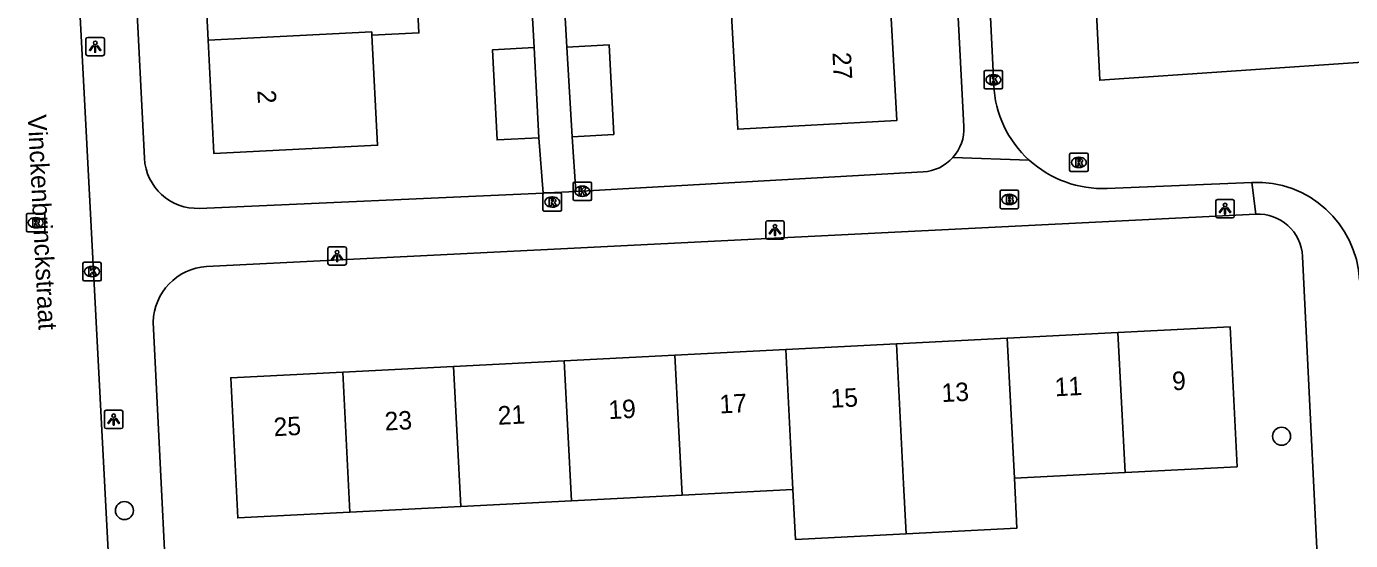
# Model space of a CAD drawing. Extents: x 160557 to 161245, y 385330 to 386505.
# Drawn here: x 161000.9 to 161072.6, y 385390.8 to 385418.6 of the extents above; entities that cross this region are included whole.
import ezdxf

# ---------------------------------------------------------------- set-up
doc = ezdxf.new("R2010")
doc.units = 0
for name, color, linetype in [('IMGEO_Boom', 7, 'Continuous'), ('IMGEO_Brandkraan', 7, 'Continuous'), ('IMGEO_Kolk', 7, 'Continuous'), ('IMGEO_Lichtpunt', 7, 'Continuous'), ('IMGEO_Openbare_ruimte_label', 7, 'Continuous'), ('IMGEO_Pand', 7, 'Continuous'), ('IMGEO_Pand_nummerreeks', 7, 'Continuous'), ('IMGEO_Rijbaan_lokaal_open', 7, 'Continuous'), ('IMGEO_Rioolput', 7, 'Continuous'), ('IMGEO_Voetpad_open', 7, 'Continuous')]:
    doc.layers.add(name, color=color, linetype=linetype)

msp = doc.modelspace()

# ---------------------------------------------------------------- linework, layer by layer
at = {"layer": 'IMGEO_Boom'}
for centre in [(161068.856, 385396.421), (161006.241, 385392.397)]:
    msp.add_circle(centre, 0.489, dxfattribs=at)
at = {"layer": 'IMGEO_Brandkraan'}
for p, q in [((161053.623, 385408.813), (161053.623, 385409.665)), ((161053.698, 385409.739), (161054.55, 385409.739)), ((161054.624, 385409.665), (161054.624, 385408.813)), ((161054.134, 385408.959), (161054.109, 385408.959)), ((161054.111, 385409.519), (161054.136, 385409.519)), ((161054.55, 385408.739), (161053.698, 385408.739))]:
    msp.add_line(p, q, dxfattribs=at)
for points in [[(161053.623, 385408.813), (161053.623, 385409.665)], [(161053.698, 385409.739), (161054.55, 385409.739)], [(161054.624, 385409.665), (161054.624, 385408.813)], [(161053.971, 385409.439), (161053.971, 385409.039), (161054.184, 385409.039)], [(161054.202, 385409.439), (161053.971, 385409.439)], [(161054.15, 385409.358), (161054.096, 385409.358), (161054.096, 385409.282)], [(161054.096, 385409.282), (161054.149, 385409.282)], [(161054.158, 385409.206), (161054.096, 385409.206), (161054.096, 385409.125)], [(161054.096, 385409.125), (161054.158, 385409.125)], [(161054.55, 385408.739), (161053.698, 385408.739)]]:
    msp.add_lwpolyline(points, dxfattribs=at)
for centre, radius, start, end in [((161053.7, 385409.663), 0.0765, 91.55205, 178.44795), ((161053.7, 385409.663), 0.0765, 91.55205, 178.44795), ((161054.548, 385409.663), 0.0765, 1.55205, 88.44795), ((161054.548, 385409.663), 0.0765, 1.55205, 88.44795), ((161054.151, 385409.32), 0.0379, 267.82845, 90.93552), ((161054.159, 385409.165), 0.0404, 269.87594, 90.50774), ((161054.19, 385409.29), 0.251, 268.66757, 293.53466), ((161054.206, 385409.294), 0.145, 59.4692, 91.53667), ((161054.231, 385409.341), 0.0922, 285.51372, 58.15012), ((161054.236, 385409.149), 0.105, 301.31148, 78.98903), ((161053.7, 385408.815), 0.0765, 181.55205, 268.44795), ((161053.7, 385408.815), 0.0765, 181.55205, 268.44795), ((161054.548, 385408.815), 0.0765, 271.55205, 358.44795), ((161054.548, 385408.815), 0.0765, 271.55205, 358.44795)]:
    msp.add_arc(centre, radius, start, end, dxfattribs=at)
for centre, major_axis, ratio, start_param, end_param in [((161054.11, 385409.239), (-0.387, 0.002), 0.722429, 4.712389, 7.853982), ((161054.135, 385409.239), (-0.39, 0.002), 0.717154, 1.570796, 4.712389)]:
    msp.add_ellipse(centre, major_axis=major_axis, ratio=ratio, start_param=start_param, end_param=end_param, dxfattribs=at)
at = {"layer": 'IMGEO_Kolk'}
for p, q in [((161052.764, 385415.297), (161052.764, 385416.149)), ((161052.839, 385416.223), (161053.691, 385416.223)), ((161053.765, 385416.149), (161053.765, 385415.297)), ((161053.275, 385415.443), (161053.25, 385415.443)), ((161053.252, 385416.003), (161053.277, 385416.003)), ((161053.691, 385415.223), (161052.839, 385415.223)), ((161030.52, 385409.255), (161030.52, 385410.107)), ((161030.595, 385410.181), (161031.447, 385410.181)), ((161031.008, 385409.961), (161031.033, 385409.961)), ((161031.521, 385410.107), (161031.521, 385409.255)), ((161031.447, 385409.181), (161030.595, 385409.181)), ((161031.031, 385409.401), (161031.006, 385409.401)), ((161003.987, 385404.911), (161003.987, 385405.763)), ((161004.062, 385405.837), (161004.914, 385405.837)), ((161004.475, 385405.617), (161004.5, 385405.617)), ((161004.988, 385405.763), (161004.988, 385404.911)), ((161004.914, 385404.837), (161004.062, 385404.837)), ((161004.498, 385405.057), (161004.473, 385405.057))]:
    msp.add_line(p, q, dxfattribs=at)
for points in [[(161052.764, 385415.297), (161052.764, 385416.149)], [(161052.839, 385416.223), (161053.691, 385416.223)], [(161053.765, 385416.149), (161053.765, 385415.297)], [(161053.085, 385415.923), (161053.208, 385415.923), (161053.208, 385415.772), (161053.338, 385415.923), (161053.502, 385415.923), (161053.356, 385415.772), (161053.509, 385415.523), (161053.357, 385415.523), (161053.272, 385415.687), (161053.208, 385415.62), (161053.208, 385415.523), (161053.085, 385415.523), (161053.085, 385415.923)], [(161053.691, 385415.223), (161052.839, 385415.223)], [(161030.52, 385409.255), (161030.52, 385410.107)], [(161030.595, 385410.181), (161031.447, 385410.181)], [(161030.841, 385409.881), (161030.964, 385409.881), (161030.964, 385409.73), (161031.094, 385409.881), (161031.258, 385409.881), (161031.112, 385409.73), (161031.265, 385409.481), (161031.113, 385409.481), (161031.028, 385409.645), (161030.964, 385409.578), (161030.964, 385409.481), (161030.841, 385409.481), (161030.841, 385409.881)], [(161031.521, 385410.107), (161031.521, 385409.255)], [(161031.447, 385409.181), (161030.595, 385409.181)], [(161003.987, 385404.911), (161003.987, 385405.763)], [(161004.062, 385405.837), (161004.914, 385405.837)], [(161004.308, 385405.537), (161004.431, 385405.537), (161004.431, 385405.386), (161004.561, 385405.537), (161004.725, 385405.537), (161004.579, 385405.386), (161004.732, 385405.137), (161004.58, 385405.137), (161004.495, 385405.301), (161004.431, 385405.234), (161004.431, 385405.137), (161004.308, 385405.137), (161004.308, 385405.537)], [(161004.988, 385405.763), (161004.988, 385404.911)], [(161004.914, 385404.837), (161004.062, 385404.837)]]:
    msp.add_lwpolyline(points, dxfattribs=at)
for centre, start, end in [((161052.841, 385416.147), 91.55205, 178.44795), ((161052.841, 385416.147), 91.55205, 178.44795), ((161053.689, 385416.147), 1.55205, 88.44795), ((161053.689, 385416.147), 1.55205, 88.44795), ((161052.841, 385415.299), 181.55205, 268.44795), ((161052.841, 385415.299), 181.55205, 268.44795), ((161053.689, 385415.299), 271.55205, 358.44795), ((161053.689, 385415.299), 271.55205, 358.44795), ((161030.597, 385410.105), 91.55205, 178.44795), ((161030.597, 385410.105), 91.55205, 178.44795), ((161031.445, 385410.105), 1.55205, 88.44795), ((161031.445, 385410.105), 1.55205, 88.44795), ((161030.597, 385409.257), 181.55205, 268.44795), ((161030.597, 385409.257), 181.55205, 268.44795), ((161031.445, 385409.257), 271.55205, 358.44795), ((161031.445, 385409.257), 271.55205, 358.44795), ((161004.064, 385405.761), 91.55205, 178.44795), ((161004.064, 385405.761), 91.55205, 178.44795), ((161004.912, 385405.761), 1.55205, 88.44795), ((161004.912, 385405.761), 1.55205, 88.44795), ((161004.064, 385404.913), 181.55205, 268.44795), ((161004.064, 385404.913), 181.55205, 268.44795), ((161004.912, 385404.913), 271.55205, 358.44795), ((161004.912, 385404.913), 271.55205, 358.44795)]:
    msp.add_arc(centre, 0.0765, start, end, dxfattribs=at)
for centre, major_axis, ratio, start_param, end_param in [((161053.251, 385415.723), (-0.387, 0.002), 0.722429, 4.712389, 7.853982), ((161053.276, 385415.723), (-0.39, 0.002), 0.717154, 1.570796, 4.712389), ((161031.007, 385409.681), (-0.387, 0.002), 0.722429, 4.712389, 7.853982), ((161031.032, 385409.681), (-0.39, 0.002), 0.717154, 1.570796, 4.712389), ((161004.474, 385405.337), (-0.387, 0.002), 0.722429, 4.712389, 7.853982), ((161004.499, 385405.337), (-0.39, 0.002), 0.717154, 1.570796, 4.712389)]:
    msp.add_ellipse(centre, major_axis=major_axis, ratio=ratio, start_param=start_param, end_param=end_param, dxfattribs=at)
at = {"layer": 'IMGEO_Lichtpunt'}
for p, q in [((161004.159, 385417.918), (161004.159, 385417.111)), ((161004.159, 385417.918), (161004.159, 385417.111)), ((161005.061, 385418.013), (161004.253, 385418.013)), ((161005.061, 385418.013), (161004.253, 385418.013)), ((161005.155, 385417.111), (161005.155, 385417.918)), ((161005.155, 385417.111), (161005.155, 385417.918)), ((161004.253, 385417.017), (161005.061, 385417.017)), ((161004.253, 385417.017), (161005.061, 385417.017)), ((161065.3, 385409.143), (161065.3, 385408.336)), ((161065.3, 385409.143), (161065.3, 385408.336)), ((161066.202, 385409.238), (161065.394, 385409.238)), ((161066.202, 385409.238), (161065.394, 385409.238)), ((161066.296, 385408.336), (161066.296, 385409.143)), ((161066.296, 385408.336), (161066.296, 385409.143)), ((161065.394, 385408.242), (161066.202, 385408.242)), ((161065.394, 385408.242), (161066.202, 385408.242)), ((161040.945, 385407.989), (161040.945, 385407.182)), ((161040.945, 385407.989), (161040.945, 385407.182)), ((161041.847, 385408.084), (161041.039, 385408.084)), ((161041.847, 385408.084), (161041.039, 385408.084)), ((161041.941, 385407.182), (161041.941, 385407.989)), ((161041.941, 385407.182), (161041.941, 385407.989)), ((161041.039, 385407.088), (161041.847, 385407.088)), ((161041.039, 385407.088), (161041.847, 385407.088)), ((161017.253, 385406.584), (161017.253, 385405.777)), ((161017.253, 385406.584), (161017.253, 385405.777)), ((161018.155, 385406.679), (161017.347, 385406.679)), ((161018.155, 385406.679), (161017.347, 385406.679)), ((161018.249, 385405.777), (161018.249, 385406.584)), ((161018.249, 385405.777), (161018.249, 385406.584)), ((161017.347, 385405.683), (161018.155, 385405.683)), ((161017.347, 385405.683), (161018.155, 385405.683)), ((161005.161, 385397.736), (161005.161, 385396.929)), ((161005.161, 385397.736), (161005.161, 385396.929)), ((161006.063, 385397.831), (161005.255, 385397.831)), ((161006.063, 385397.831), (161005.255, 385397.831)), ((161006.157, 385396.929), (161006.157, 385397.736)), ((161006.157, 385396.929), (161006.157, 385397.736)), ((161005.255, 385396.835), (161006.063, 385396.835)), ((161005.255, 385396.835), (161006.063, 385396.835))]:
    msp.add_line(p, q, dxfattribs=at)
for points in [[(161004.533, 385417.582), (161004.572, 385417.554), (161004.384, 385417.292), (161004.346, 385417.319), (161004.533, 385417.582)], [(161004.635, 385417.534), (161004.682, 385417.534), (161004.682, 385417.212), (161004.635, 385417.212), (161004.635, 385417.534)], [(161004.745, 385417.554), (161004.783, 385417.581), (161004.97, 385417.319), (161004.931, 385417.291), (161004.745, 385417.554)], [(161065.674, 385408.807), (161065.713, 385408.779), (161065.525, 385408.517), (161065.487, 385408.544), (161065.674, 385408.807)], [(161065.776, 385408.759), (161065.823, 385408.759), (161065.823, 385408.437), (161065.776, 385408.437), (161065.776, 385408.759)], [(161065.886, 385408.779), (161065.924, 385408.806), (161066.111, 385408.544), (161066.072, 385408.516), (161065.886, 385408.779)], [(161041.319, 385407.653), (161041.358, 385407.625), (161041.17, 385407.363), (161041.132, 385407.39), (161041.319, 385407.653)], [(161041.421, 385407.605), (161041.468, 385407.605), (161041.468, 385407.283), (161041.421, 385407.283), (161041.421, 385407.605)], [(161041.531, 385407.625), (161041.569, 385407.652), (161041.756, 385407.39), (161041.717, 385407.362), (161041.531, 385407.625)], [(161017.627, 385406.248), (161017.666, 385406.22), (161017.478, 385405.958), (161017.44, 385405.985), (161017.627, 385406.248)], [(161017.729, 385406.2), (161017.776, 385406.2), (161017.776, 385405.878), (161017.729, 385405.878), (161017.729, 385406.2)], [(161017.839, 385406.22), (161017.877, 385406.247), (161018.064, 385405.985), (161018.025, 385405.957), (161017.839, 385406.22)], [(161005.535, 385397.4), (161005.574, 385397.372), (161005.386, 385397.11), (161005.348, 385397.137), (161005.535, 385397.4)], [(161005.637, 385397.352), (161005.684, 385397.352), (161005.684, 385397.03), (161005.637, 385397.03), (161005.637, 385397.352)], [(161005.747, 385397.372), (161005.785, 385397.399), (161005.972, 385397.137), (161005.933, 385397.109), (161005.747, 385397.372)]]:
    msp.add_lwpolyline(points, dxfattribs=at)
for centre in [(161004.658, 385417.716), (161065.799, 385408.941), (161041.444, 385407.787), (161017.752, 385406.382), (161005.66, 385397.534)]:
    msp.add_circle(centre, 0.0994, dxfattribs=at)
for centre, start, end in [((161004.253, 385417.918), 90, 180), ((161004.253, 385417.918), 90, 180), ((161005.061, 385417.918), 0, 90), ((161005.061, 385417.918), 0, 90), ((161004.253, 385417.111), 180, 270), ((161004.253, 385417.111), 180, 270), ((161005.061, 385417.111), 270, 0), ((161005.061, 385417.111), 270, 360), ((161065.394, 385409.143), 90, 180), ((161065.394, 385409.143), 90, 180), ((161066.202, 385409.143), 0, 90), ((161066.202, 385409.143), 0, 90), ((161065.394, 385408.336), 180, 270), ((161065.394, 385408.336), 180, 270), ((161066.202, 385408.336), 270, 0), ((161066.202, 385408.336), 270, 360), ((161041.039, 385407.989), 90, 180), ((161041.039, 385407.989), 90, 180), ((161041.847, 385407.989), 0, 90), ((161041.847, 385407.989), 0, 90), ((161041.039, 385407.182), 180, 270), ((161041.039, 385407.182), 180, 270), ((161041.847, 385407.182), 270, 0), ((161041.847, 385407.182), 270, 360), ((161017.347, 385406.584), 90, 180), ((161017.347, 385406.584), 90, 180), ((161018.155, 385406.584), 0, 90), ((161018.155, 385406.584), 0, 90), ((161017.347, 385405.777), 180, 270), ((161017.347, 385405.777), 180, 270), ((161018.155, 385405.777), 270, 0), ((161018.155, 385405.777), 270, 360), ((161005.255, 385397.736), 90, 180), ((161005.255, 385397.736), 90, 180), ((161006.063, 385397.736), 0, 90), ((161006.063, 385397.736), 0, 90), ((161005.255, 385396.929), 180, 270), ((161005.255, 385396.929), 180, 270), ((161006.063, 385396.929), 270, 0), ((161006.063, 385396.929), 270, 360)]:
    msp.add_arc(centre, 0.0946, start, end, dxfattribs=at)
at = {"layer": 'IMGEO_Pand'}
for points in [[(161019.634, 385418.125), (161022.181, 385418.255), (161021.883, 385424.097), (161019.335, 385423.967), (161019.318, 385424.303)], [(161010.464, 385423.853), (161010.77, 385417.861)], [(161047.7, 385419.697), (161048.038, 385413.509), (161039.428, 385413.039), (161039.09, 385419.226)], [(161010.77, 385417.861), (161019.624, 385418.311), (161019.634, 385418.125)], [(161019.634, 385418.125), (161019.938, 385412.178), (161011.084, 385411.725), (161010.77, 385417.861)], [(161030.461, 385412.629), (161032.721, 385412.761), (161032.464, 385417.618), (161030.177, 385417.484)], [(161028.405, 385417.461), (161026.159, 385417.347), (161026.408, 385412.465), (161028.672, 385412.58)], [(161028.672, 385412.58), (161028.405, 385417.461)], [(161030.177, 385417.484), (161030.461, 385412.629)], [(161054.01, 385401.733), (161060.002, 385402.04)], [(161060.002, 385402.04), (161066.07, 385402.35), (161066.455, 385394.77), (161060.39, 385394.459)], [(161060.002, 385402.04), (161060.39, 385394.459)], [(161036.033, 385400.814), (161042.026, 385401.121)], [(161042.026, 385401.121), (161048.018, 385401.427)], [(161042.026, 385401.121), (161042.414, 385393.539)], [(161048.018, 385401.427), (161054.01, 385401.733)], [(161048.018, 385401.427), (161048.406, 385393.846), (161048.544, 385391.147)], [(161054.398, 385394.152), (161054.01, 385401.733)], [(161024.049, 385400.201), (161030.041, 385400.508)], [(161030.041, 385400.508), (161036.033, 385400.814)], [(161030.041, 385400.508), (161030.429, 385392.925)], [(161036.421, 385393.232), (161036.033, 385400.814)], [(161018.445, 385392.311), (161012.375, 385392), (161011.99, 385399.585), (161018.057, 385399.895)], [(161018.057, 385399.895), (161024.049, 385400.201)], [(161018.057, 385399.895), (161018.445, 385392.311)], [(161024.437, 385392.618), (161024.049, 385400.201)], [(161054.398, 385394.152), (161054.536, 385391.453), (161048.544, 385391.147)], [(161060.39, 385394.459), (161054.398, 385394.152)], [(161036.421, 385393.232), (161030.429, 385392.925)], [(161042.414, 385393.539), (161036.421, 385393.232)], [(161048.544, 385391.147), (161042.552, 385390.84), (161042.414, 385393.539)], [(161024.437, 385392.618), (161018.445, 385392.311)], [(161030.429, 385392.925), (161024.437, 385392.618)]]:
    msp.add_lwpolyline(points, dxfattribs=at)
at = {"layer": 'IMGEO_Rijbaan_lokaal_open'}
for points in [[(161072.491, 385441.37), (161057.78, 385440.68), (161059.018, 385415.696), (161073.778, 385416.7), (161072.491, 385441.37)], [(161053.28, 385415.442), (161052.056, 385440.315)], [(161002.852, 385438.071), (161005.785, 385381.954)], [(161067.252, 385410.167), (161059.425, 385409.835)]]:
    msp.add_lwpolyline(points, dxfattribs=at)
for centre, radius, start, end in [((161059.179, 385415.734), 5.907, 182.83591, 227.60566), ((161059.176, 385415.734), 5.904, 227.62897, 272.4157), ((161067.491, 385404.582), 5.59, 2.93447, 92.45059)]:
    msp.add_arc(centre, radius, start, end, dxfattribs=at)
at = {"layer": 'IMGEO_Rioolput'}
for p, q in [((161057.387, 385410.82), (161057.387, 385411.672)), ((161057.462, 385411.746), (161058.314, 385411.746)), ((161057.875, 385411.526), (161057.9, 385411.526)), ((161058.388, 385411.672), (161058.388, 385410.82)), ((161058.314, 385410.746), (161057.462, 385410.746)), ((161057.898, 385410.966), (161057.873, 385410.966)), ((161028.887, 385408.676), (161028.887, 385409.528)), ((161028.962, 385409.602), (161029.814, 385409.602)), ((161029.375, 385409.382), (161029.4, 385409.382)), ((161029.888, 385409.528), (161029.888, 385408.676)), ((161000.94, 385407.557), (161000.94, 385408.409)), ((161001.015, 385408.483), (161001.867, 385408.483)), ((161001.428, 385408.263), (161001.453, 385408.263)), ((161001.941, 385408.409), (161001.941, 385407.557)), ((161029.814, 385408.602), (161028.962, 385408.602)), ((161029.398, 385408.822), (161029.373, 385408.822)), ((161001.867, 385407.483), (161001.015, 385407.483)), ((161001.451, 385407.703), (161001.426, 385407.703))]:
    msp.add_line(p, q, dxfattribs=at)
for points in [[(161057.387, 385410.82), (161057.387, 385411.672)], [(161057.462, 385411.746), (161058.314, 385411.746)], [(161057.976, 385411.444), (161057.724, 385411.446), (161057.724, 385411.046)], [(161057.724, 385411.046), (161057.848, 385411.046), (161057.848, 385411.208), (161057.859, 385411.208)], [(161057.902, 385411.365), (161057.848, 385411.365), (161057.848, 385411.284)], [(161057.848, 385411.284), (161057.9, 385411.284)], [(161057.906, 385411.179), (161057.977, 385411.046), (161058.117, 385411.046), (161058.052, 385411.172)], [(161058.388, 385411.672), (161058.388, 385410.82)], [(161058.314, 385410.746), (161057.462, 385410.746)], [(161028.887, 385408.676), (161028.887, 385409.528)], [(161028.962, 385409.602), (161029.814, 385409.602)], [(161029.476, 385409.3), (161029.224, 385409.302), (161029.224, 385408.902)], [(161029.224, 385408.902), (161029.348, 385408.902), (161029.348, 385409.064), (161029.359, 385409.064)], [(161029.402, 385409.221), (161029.348, 385409.221), (161029.348, 385409.14)], [(161029.348, 385409.14), (161029.4, 385409.14)], [(161029.406, 385409.035), (161029.477, 385408.902), (161029.617, 385408.902), (161029.552, 385409.028)], [(161029.888, 385409.528), (161029.888, 385408.676)], [(161000.94, 385407.557), (161000.94, 385408.409)], [(161001.015, 385408.483), (161001.867, 385408.483)], [(161001.941, 385408.409), (161001.941, 385407.557)], [(161029.814, 385408.602), (161028.962, 385408.602)], [(161001.867, 385407.483), (161001.015, 385407.483)], [(161001.529, 385408.181), (161001.277, 385408.183), (161001.277, 385407.783)], [(161001.277, 385407.783), (161001.401, 385407.783), (161001.401, 385407.945), (161001.412, 385407.945)], [(161001.455, 385408.102), (161001.401, 385408.102), (161001.401, 385408.021)], [(161001.401, 385408.021), (161001.453, 385408.021)], [(161001.459, 385407.916), (161001.53, 385407.783), (161001.67, 385407.783), (161001.605, 385407.909)]]:
    msp.add_lwpolyline(points, dxfattribs=at)
for centre, radius, start, end in [((161057.464, 385411.67), 0.0765, 91.55205, 178.44795), ((161057.464, 385411.67), 0.0765, 91.55205, 178.44795), ((161057.858, 385411.155), 0.0533, 26.02933, 88.69889), ((161057.884, 385411.473), 0.19, 274.7715, 282.96867), ((161057.908, 385411.269), 0.0964, 77.00612, 93.18647), ((161057.922, 385411.326), 0.0378, 276.66336, 79.67722), ((161057.975, 385411.334), 0.109, 350.36119, 89.41601), ((161057.973, 385411.334), 0.112, 277.58423, 350.98172), ((161057.957, 385411.119), 0.108, 29.51342, 73.79051), ((161058.312, 385411.67), 0.0765, 1.55205, 88.44795), ((161058.312, 385411.67), 0.0765, 1.55205, 88.44795), ((161057.464, 385410.822), 0.0765, 181.55205, 268.44795), ((161057.464, 385410.822), 0.0765, 181.55205, 268.44795), ((161058.312, 385410.822), 0.0765, 271.55205, 358.44795), ((161058.312, 385410.822), 0.0765, 271.55205, 358.44795), ((161028.964, 385409.526), 0.0765, 91.55205, 178.44795), ((161028.964, 385409.526), 0.0765, 91.55205, 178.44795), ((161029.358, 385409.011), 0.0533, 26.02933, 88.69889), ((161029.384, 385409.329), 0.19, 274.7715, 282.96867), ((161029.408, 385409.125), 0.0964, 77.00612, 93.18647), ((161029.422, 385409.182), 0.0378, 276.66336, 79.67722), ((161029.475, 385409.19), 0.109, 350.36119, 89.41601), ((161029.473, 385409.19), 0.112, 277.58423, 350.98172), ((161029.457, 385408.975), 0.108, 29.51342, 73.79051), ((161029.812, 385409.526), 0.0765, 1.55205, 88.44795), ((161029.812, 385409.526), 0.0765, 1.55205, 88.44795), ((161001.017, 385408.407), 0.0765, 91.55205, 178.44795), ((161001.017, 385408.407), 0.0765, 91.55205, 178.44795), ((161001.865, 385408.407), 0.0765, 1.55205, 88.44795), ((161001.865, 385408.407), 0.0765, 1.55205, 88.44795), ((161028.964, 385408.678), 0.0765, 181.55205, 268.44795), ((161028.964, 385408.678), 0.0765, 181.55205, 268.44795), ((161029.812, 385408.678), 0.0765, 271.55205, 358.44795), ((161029.812, 385408.678), 0.0765, 271.55205, 358.44795), ((161001.017, 385407.559), 0.0765, 181.55205, 268.44795), ((161001.017, 385407.559), 0.0765, 181.55205, 268.44795), ((161001.411, 385407.892), 0.0533, 26.02933, 88.69889), ((161001.437, 385408.21), 0.19, 274.7715, 282.96867), ((161001.461, 385408.006), 0.0964, 77.00612, 93.18647), ((161001.475, 385408.063), 0.0378, 276.66336, 79.67722), ((161001.528, 385408.071), 0.109, 350.36119, 89.41601), ((161001.526, 385408.071), 0.112, 277.58423, 350.98172), ((161001.51, 385407.856), 0.108, 29.51342, 73.79051), ((161001.865, 385407.559), 0.0765, 271.55205, 358.44795), ((161001.865, 385407.559), 0.0765, 271.55205, 358.44795)]:
    msp.add_arc(centre, radius, start, end, dxfattribs=at)
for centre, major_axis, ratio, start_param, end_param in [((161057.874, 385411.246), (-0.387, 0.002), 0.722429, 4.712389, 7.853982), ((161057.899, 385411.246), (-0.39, 0.002), 0.717154, 1.570796, 4.712389), ((161029.374, 385409.102), (-0.387, 0.002), 0.722429, 4.712389, 7.853982), ((161029.399, 385409.102), (-0.39, 0.002), 0.717154, 1.570796, 4.712389), ((161001.427, 385407.983), (-0.387, 0.002), 0.722429, 4.712389, 7.853982), ((161001.452, 385407.983), (-0.39, 0.002), 0.717154, 1.570796, 4.712389)]:
    msp.add_ellipse(centre, major_axis=major_axis, ratio=ratio, start_param=start_param, end_param=end_param, dxfattribs=at)
at = {"layer": 'IMGEO_Voetpad_open'}
for points in [[(161007.323, 385411.475), (161004.397, 385469.086)], [(161051.668, 385413.192), (161050.066, 385444.139)], [(161028.263, 385420.033), (161028.405, 385417.461)], [(161030.177, 385417.484), (161030.042, 385420.061)], [(161028.672, 385412.58), (161028.903, 385409.588)], [(161030.669, 385409.667), (161030.461, 385412.629)], [(161055.197, 385411.372), (161051.072, 385411.509)], [(161049.465, 385410.731), (161030.669, 385409.667)], [(161028.903, 385409.588), (161029.129, 385409.598), (161030.669, 385409.667)], [(161067.457, 385408.451), (161067.252, 385410.167)], [(161028.903, 385409.588), (161010.309, 385408.759)], [(161067.457, 385408.451), (161010.683, 385405.609)], [(161071.191, 385381.596), (161071.173, 385381.973), (161071.052, 385384.463), (161069.996, 385406.154)], [(161007.798, 385402.601), (161008.862, 385381.195), (161009.002, 385378.4)]]:
    msp.add_lwpolyline(points, dxfattribs=at)
for centre, radius, start, end in [((161049.319, 385413.077), 2.352, 318.19267, 2.80622), ((161010.182, 385411.619), 2.863, 182.87952, 272.54255), ((161049.323, 385413.073), 2.347, 273.47213, 318.19408), ((161067.577, 385406.032), 2.422, 2.88795, 92.84159), ((161010.879, 385402.534), 3.081, 93.63967, 178.75176)]:
    msp.add_arc(centre, radius, start, end, dxfattribs=at)

# ---------------------------------------------------------------- texts
at = {"layer": 'IMGEO_Openbare_ruimte_label'}
msp.add_text('Vinckenbrinckstraat', height=1, rotation=272.92247, dxfattribs=at).set_placement((161001.007, 385413.808))
at = {"layer": 'IMGEO_Pand_nummerreeks'}
for s, rotation, p in [('27', 273.13058, (161044.552, 385417.19)), ('2', 272.9276, (161013.433, 385415.144)), ('11', 2.92687, (161056.604, 385398.582)), ('9', 2.92687, (161062.959, 385398.906)), ('15', 2.92781, (161044.472, 385397.962)), ('13', 2.92781, (161050.481, 385398.269)), ('19', 2.92687, (161032.454, 385397.347)), ('17', 2.92687, (161038.463, 385397.654)), ('25', 2.92687, (161014.337, 385396.42)), ('23', 2.92687, (161020.345, 385396.728)), ('21', 2.92687, (161026.467, 385397.041))]:
    msp.add_text(s, height=1, rotation=rotation, dxfattribs=at).set_placement(p)

doc.saveas('drawing.dxf')
